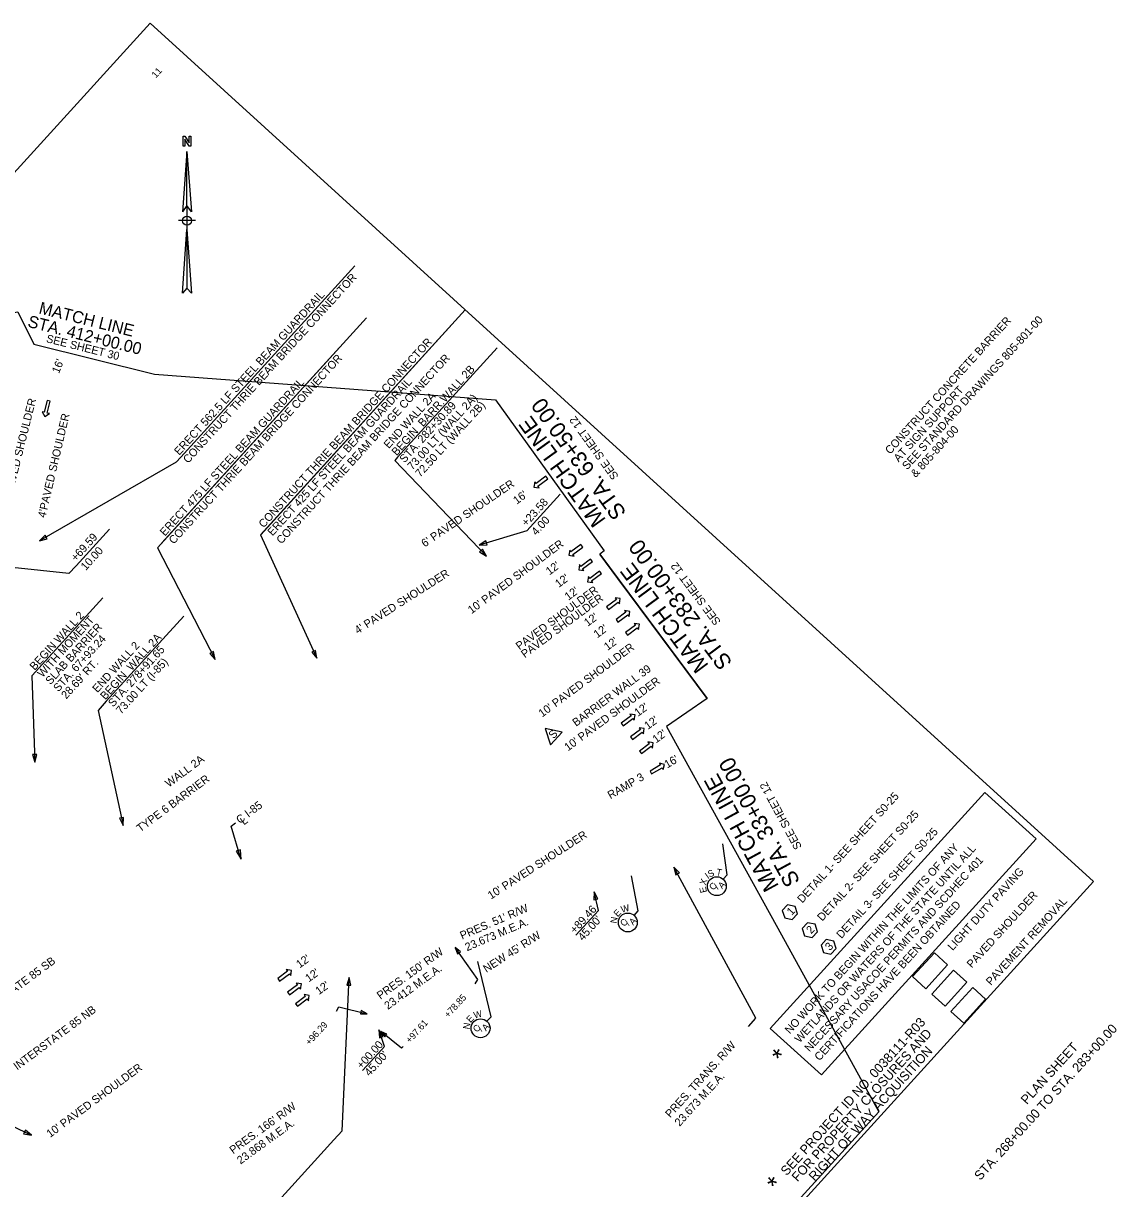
# Model space of a CAD drawing. Extents: x 1608705 to 1610581, y 1091647 to 1093887.
# Drawn here: x 1609761 to 1610581, y 1093011 to 1093885 of the extents above; entities that cross this region are included whole.
import ezdxf

# ---------------------------------------------------------------- set-up
doc = ezdxf.new("R2010")
doc.units = 0
for name, color, linetype in [('Level 1', 7, 'Continuous'), ('Level 14', 7, 'Continuous'), ('Level 2', 7, 'Continuous'), ('Plan_Clip', 7, 'Continuous'), ('RD_EX_Control_Access', 7, 'Continuous'), ('RD_EX_RW_TX', 7, 'Continuous'), ('RD_PD_GR_TX', 7, 'Continuous'), ('RD_PD_RW_TX', 7, 'Continuous'), ('RD_SHT_MatchLine', 7, 'Continuous'), ('RD_SHT_TX', 7, 'Continuous'), ('RD_TX_RoadID', 7, 'Continuous'), ('RD_TX_RW', 7, 'Continuous')]:
    doc.layers.add(name, color=color, linetype=linetype)

msp = doc.modelspace()

# ---------------------------------------------------------------- linework, layer by layer
at = {"layer": 'Level 1'}
for p, q in [((1609883.63, 1093788.5), (1609880.22, 1093743.19)), ((1609883.63, 1093747.84), (1609880.22, 1093743.19)), ((1609883.63, 1093747.84), (1609883.63, 1093730)), ((1609890.15, 1093736.61), (1609877.18, 1093736.61)), ((1609883.63, 1093730), (1609887.05, 1093682.16)), ((1609887.05, 1093682.16), (1609883.63, 1093685.99))]:
    msp.add_line(p, q, dxfattribs=at)
msp.add_lwpolyline([(1609886.57, 1093792.33), (1609885.34, 1093792.33), (1609881.92, 1093797.8), (1609881.92, 1093796.98), (1609881.92, 1093792.33), (1609880.69, 1093792.33), (1609880.69, 1093799.92), (1609881.92, 1093799.92), (1609885.34, 1093794.86), (1609885.34, 1093795.27), (1609885.34, 1093799.92), (1609886.57, 1093799.92), (1609886.57, 1093792.33)], dxfattribs=at)
for points in [[(1609883.63, 1093788.5), (1609887.05, 1093743.19), (1609883.63, 1093747.84)], [(1609883.63, 1093730), (1609883.63, 1093685.99), (1609880.22, 1093682.16)]]:
    msp.add_lwpolyline(points, close=True, dxfattribs=at)
msp.add_circle((1609883.67, 1093736.61), 3.45, dxfattribs=at)
at = {"layer": 'Level 14'}
for points in [[(1609781.09, 1093601.22), (1609778.76, 1093601.8), (1609776.55, 1093592.89), (1609774.97, 1093593.29), (1609777.03, 1093589.86), (1609780.46, 1093591.92), (1609778.87, 1093592.32)], [(1610154.27, 1093543.02), (1610152.84, 1093544.95), (1610145.48, 1093539.48), (1610144.51, 1093540.79), (1610143.93, 1093536.83), (1610147.88, 1093536.25), (1610146.91, 1093537.55)], [(1610180.49, 1093491.85), (1610179.06, 1093493.78), (1610171.69, 1093488.31), (1610170.72, 1093489.62), (1610170.14, 1093485.66), (1610174.1, 1093485.08), (1610173.13, 1093486.38)], [(1610187.82, 1093480.93), (1610186.39, 1093482.86), (1610179.03, 1093477.39), (1610178.06, 1093478.7), (1610177.48, 1093474.74), (1610181.43, 1093474.16), (1610180.46, 1093475.46)], [(1610194.52, 1093471.93), (1610193.09, 1093473.85), (1610185.72, 1093468.38), (1610184.75, 1093469.69), (1610184.17, 1093465.73), (1610188.13, 1093465.15), (1610187.16, 1093466.46)], [(1610198.36, 1093447.02), (1610199.79, 1093445.09), (1610207.15, 1093450.56), (1610208.12, 1093449.25), (1610208.7, 1093453.21), (1610204.75, 1093453.79), (1610205.72, 1093452.49)], [(1610205.48, 1093437.44), (1610206.91, 1093435.51), (1610214.27, 1093440.98), (1610215.24, 1093439.67), (1610215.82, 1093443.63), (1610211.87, 1093444.21), (1610212.84, 1093442.91)], [(1610212.65, 1093427.79), (1610214.08, 1093425.86), (1610221.44, 1093431.33), (1610222.41, 1093430.02), (1610223, 1093433.98), (1610219.04, 1093434.56), (1610220.01, 1093433.26)], [(1610209.38, 1093359.73), (1610210.82, 1093357.81), (1610218.17, 1093363.28), (1610219.15, 1093361.98), (1610219.73, 1093365.93), (1610215.77, 1093366.51), (1610216.74, 1093365.21)], [(1610216.36, 1093349.54), (1610217.79, 1093347.61), (1610225.15, 1093353.09), (1610226.12, 1093351.78), (1610226.7, 1093355.74), (1610222.75, 1093356.32), (1610223.72, 1093355.01)], [(1610223.08, 1093338.91), (1610224.52, 1093336.98), (1610231.88, 1093342.46), (1610232.85, 1093341.15), (1610233.43, 1093345.11), (1610229.47, 1093345.69), (1610230.44, 1093344.38)], [(1610231, 1093323.8), (1610232.21, 1093321.73), (1610240.13, 1093326.37), (1610240.95, 1093324.96), (1610241.96, 1093328.83), (1610238.09, 1093329.84), (1610238.91, 1093328.44)], [(1609951.7, 1093168.27), (1609953.14, 1093166.35), (1609960.5, 1093171.82), (1609961.47, 1093170.51), (1609962.05, 1093174.47), (1609958.09, 1093175.05), (1609959.07, 1093173.74)], [(1609959.12, 1093158.13), (1609960.55, 1093156.2), (1609967.91, 1093161.67), (1609968.88, 1093160.36), (1609969.46, 1093164.32), (1609965.51, 1093164.9), (1609966.48, 1093163.6)], [(1609965.06, 1093149.46), (1609966.49, 1093147.53), (1609973.86, 1093153), (1609974.83, 1093151.7), (1609975.41, 1093155.65), (1609971.45, 1093156.24), (1609972.42, 1093154.93)]]:
    msp.add_lwpolyline(points, close=True, dxfattribs=at)
at = {"layer": 'Level 2'}
msp.add_lwpolyline([(1608729.11, 1092645.4), (1609856.11, 1093884.55), (1610563.72, 1093240.99), (1609436.73, 1092001.83)], close=True, dxfattribs=at)
at = {"layer": 'Plan_Clip'}
msp.add_lwpolyline([(1609149.57, 1092364.39), (1609089.98, 1092453.43), (1608942.04, 1092657.59), (1608947.36, 1092661.14), (1608865.54, 1092773.4), (1609629.05, 1093625.07), (1609624.58, 1093628.85), (1609641.66, 1093647.8), (1609756.72, 1093668.33), (1609768.78, 1093644.04), (1609859.36, 1093621.37), (1610115.12, 1093602.27), (1610196.6, 1093489.1), (1610193.26, 1093486.62), (1610273.82, 1093378.23), (1610243.45, 1093357.42), (1610329.63, 1093200.98), (1610402.66, 1093068.39), (1609510.9, 1092089.32)], dxfattribs=at)
msp.add_lwpolyline([(1609149.57, 1092364.39), (1609089.98, 1092453.43), (1608942.04, 1092657.59), (1608947.36, 1092661.14), (1608865.54, 1092773.4), (1609629.05, 1093625.07), (1609624.58, 1093628.85), (1609641.66, 1093647.8), (1609756.72, 1093668.33), (1609768.78, 1093644.04), (1609859.36, 1093621.37), (1610115.12, 1093602.27), (1610196.6, 1093489.1), (1610193.26, 1093486.62), (1610273.82, 1093378.23), (1610243.45, 1093357.42), (1610329.63, 1093200.98), (1610402.66, 1093068.39), (1609510.9, 1092089.32)], dxfattribs=at)
at = {"layer": 'RD_EX_Control_Access'}
for p, q in [((1610288.92, 1093246.18), (1610285.73, 1093269.24)), ((1610222.14, 1093219.01), (1610217.11, 1093245.39)), ((1610285.84, 1093242.79), (1610288.92, 1093246.18)), ((1610219.06, 1093215.63), (1610222.14, 1093219.01)), ((1610111.72, 1093139.66), (1610101.86, 1093181.04)), ((1610108.64, 1093136.27), (1610111.72, 1093139.66))]:
    msp.add_line(p, q, dxfattribs=at)
for centre in [(1610281.07, 1093237.55), (1610214.3, 1093210.38), (1610103.87, 1093131.03)]:
    msp.add_circle(centre, 7.08, dxfattribs=at)
at = {"layer": 'RD_EX_RW_TX'}
for points in [[(1610304.85, 1093132.45), (1610310.35, 1093138.49), (1610248.96, 1093251.92)], [(1610099.9, 1093164.36), (1610101.88, 1093167.54), (1610084.89, 1093191.51)], [(1609995.8, 1093143.82), (1609997.59, 1093147.18), (1610018.75, 1093141.81)], [(1610045.72, 1093117.44), (1610044.63, 1093116.1), (1610029.02, 1093128.52)]]:
    msp.add_lwpolyline(points, dxfattribs=at)
for points in [[(1610253.08, 1093247.57), (1610248.96, 1093251.92), (1610250.35, 1093246.09)], [(1610088.74, 1093188.32), (1610084.89, 1093191.51), (1610086.62, 1093186.83)], [(1610013.75, 1093141.74), (1610018.75, 1093141.81), (1610014.39, 1093144.25)], [(1610033.61, 1093126.53), (1610029.02, 1093128.52), (1610032, 1093124.5)]]:
    msp.add_lwpolyline(points, close=True, dxfattribs=at)
at = {"layer": 'RD_PD_GR_TX'}
for p, q in [((1610009.48, 1093702.75), (1609878.96, 1093559.24)), ((1610092.37, 1093669.84), (1609938.92, 1093501.11)), ((1610018.27, 1093663.67), (1609864.82, 1093494.93))]:
    msp.add_line(p, q, dxfattribs=at)
for points in [[(1610092.37, 1093669.84), (1609938.75, 1093500.92), (1609981.02, 1093408.48)], [(1610018.27, 1093663.67), (1609861.42, 1093491.19), (1609904.7, 1093407.62)], [(1609878.96, 1093559.24), (1609875.55, 1093555.49), (1609773.08, 1093496.55)]]:
    msp.add_lwpolyline(points, dxfattribs=at)
for points in [[(1609777.33, 1093500.79), (1609773.08, 1093496.55), (1609778.88, 1093498.09)], [(1609900.66, 1093412.05), (1609904.7, 1093407.62), (1609903.41, 1093413.48)], [(1609977.2, 1093413.1), (1609981.02, 1093408.48), (1609980.02, 1093414.39)]]:
    msp.add_lwpolyline(points, close=True, dxfattribs=at)
at = {"layer": 'RD_SHT_MatchLine'}
for p, q in [((1609768.78, 1093644.04), (1609859.36, 1093621.37)), ((1610115.12, 1093602.27), (1610196.6, 1093489.1)), ((1610243.45, 1093357.42), (1610329.63, 1093200.98))]:
    msp.add_line(p, q, dxfattribs=at)
msp.add_lwpolyline([(1610273.82, 1093378.23), (1610206.95, 1093468.2), (1610193.26, 1093486.62)], dxfattribs=at)
at = {"layer": 'RD_SHT_TX'}
for p, q in [((1610116.29, 1093641.29), (1610041.65, 1093559.23)), ((1610163.55, 1093531.57), (1610138.48, 1093504.01)), ((1609825.55, 1093505.34), (1609800.48, 1093477.78)), ((1609820.54, 1093453.76), (1609770.13, 1093398.33)), ((1609881.17, 1093440.06), (1609823.1, 1093376.2)), ((1609993.85, 1093047.3), (1609878.33, 1092920.29))]:
    msp.add_line(p, q, dxfattribs=at)
for points in [[(1610041.65, 1093559.23), (1610039.46, 1093556.81), (1610108.21, 1093485.14)], [(1610138.48, 1093504.01), (1610138.48, 1093504.02), (1610102.81, 1093493.26)], [(1609800.48, 1093477.78), (1609795.13, 1093471.9), (1609730.94, 1093478.86)], [(1609770.22, 1093398.43), (1609767.33, 1093395.25), (1609769.63, 1093330.56)], [(1609823.1, 1093376.2), (1609816.9, 1093369.39), (1609835.67, 1093283.17)], [(1610437.89, 1093160.7), (1610454.22, 1093178.66), (1610444.27, 1093187.71), (1610427.94, 1093169.76), (1610437.89, 1093160.7)], [(1610452.27, 1093147.63), (1610468.6, 1093165.58), (1610458.64, 1093174.63), (1610442.31, 1093156.68), (1610452.27, 1093147.63)], [(1609993.85, 1093047.3), (1609999.97, 1093054.02), (1610005.32, 1093169.11)], [(1609702.19, 1093076.77), (1609705.22, 1093080.1), (1609767.01, 1093050.83)]]:
    msp.add_lwpolyline(points, dxfattribs=at)
for points in [[(1610107.91, 1093496.42), (1610102.81, 1093493.26), (1610108.8, 1093493.45)], [(1610103.08, 1093488.24), (1610108.21, 1093485.14), (1610105.32, 1093490.39)], [(1610152.31, 1093355.88), (1610156.27, 1093343.48), (1610165.03, 1093353.11)], [(1609767.87, 1093336.3), (1609769.63, 1093330.56), (1609770.97, 1093336.41)], [(1610321.19, 1093130.91), (1610482.17, 1093307.92), (1610520.53, 1093273.03), (1610359.55, 1093096.02)], [(1609832.92, 1093288.5), (1609835.67, 1093283.17), (1609835.96, 1093289.16)], [(1610339.82, 1093222.46), (1610334.14, 1093223.69), (1610330.23, 1093219.4), (1610332, 1093213.86), (1610337.67, 1093212.63), (1610341.58, 1093216.92)], [(1610354.77, 1093208.98), (1610349.1, 1093210.21), (1610345.19, 1093205.92), (1610346.96, 1093200.38), (1610352.63, 1093199.15), (1610356.54, 1093203.44)], [(1610368.88, 1093196.45), (1610363.2, 1093197.69), (1610359.29, 1093193.39), (1610361.06, 1093187.85), (1610366.74, 1093186.62), (1610370.65, 1093190.92)], [(1610437.89, 1093160.7), (1610454.22, 1093178.66), (1610444.27, 1093187.71), (1610427.94, 1093169.76)], [(1610452.27, 1093147.63), (1610468.6, 1093165.58), (1610458.64, 1093174.63), (1610442.31, 1093156.68)], [(1610006.6, 1093163.24), (1610005.32, 1093169.11), (1610003.5, 1093163.39)], [(1610466.37, 1093134.8), (1610482.7, 1093152.76), (1610473.02, 1093161.56), (1610456.69, 1093143.61)], [(1610466.35, 1093134.82), (1610482.68, 1093152.77), (1610473.02, 1093161.56), (1610456.69, 1093143.61)], [(1609761.11, 1093051.91), (1609767.01, 1093050.83), (1609762.44, 1093054.72)]]:
    msp.add_lwpolyline(points, close=True, dxfattribs=at)
at = {"layer": 'RD_TX_RoadID'}
msp.add_lwpolyline([(1609924.13, 1093257.97), (1609916.74, 1093282.66), (1609919.95, 1093285.05)], dxfattribs=at)
msp.add_lwpolyline([(1609923.91, 1093264.89), (1609920.61, 1093263.91), (1609924.24, 1093257.79)], close=True, dxfattribs=at)
at = {"layer": 'RD_TX_RW'}
for p, q in [((1610189.49, 1093216.3), (1610175.43, 1093200.84)), ((1610029.78, 1093115.22), (1610015.32, 1093099.32))]:
    msp.add_line(p, q, dxfattribs=at)
for points in [[(1610191.94, 1093228.04), (1610189.15, 1093233.35), (1610188.91, 1093227.36)], [(1610030.92, 1093124.94), (1610027.56, 1093129.92), (1610027.98, 1093123.93)]]:
    msp.add_lwpolyline(points, close=True, dxfattribs=at)
for points in [[(1610189.49, 1093216.3), (1610192.3, 1093219.39), (1610189.15, 1093233.35)], [(1610029.78, 1093115.22), (1610031.84, 1093117.49), (1610027.56, 1093129.92)]]:
    msp.add_lwpolyline(points, dxfattribs=at)

# ---------------------------------------------------------------- texts
at = {"layer": 'RD_EX_Control_Access'}
for s, rotation, p in [('S', 23.97318, (1610275.63, 1093243.98)), ('T', 348.8117, (1610280.32, 1093245.94)), ('X', 70.85514, (1610272.66, 1093237.97)), ('I', 35.69367, (1610274.44, 1093242.74)), ('E', 104.34226, (1610273.82, 1093233.26)), ('C', 47.71052, (1610278.43, 1093234.07)), ('/', 47.71052, (1610281.98, 1093234.84)), ('A', 47.71052, (1610285.14, 1093235.12)), ('W', 15.32234, (1610209.88, 1093217.56)), ('E', 47.1351, (1610206.76, 1093214.15)), ('N', 80.62222, (1610205.94, 1093209.37)), ('C', 47.71052, (1610211.65, 1093206.9)), ('/', 47.71052, (1610215.2, 1093207.67)), ('A', 47.71052, (1610218.36, 1093207.95)), ('E', 47.1351, (1610096.34, 1093134.8)), ('W', 15.32234, (1610099.46, 1093138.2)), ('N', 80.62222, (1610095.51, 1093130.02)), ('C', 47.71052, (1610101.23, 1093127.55)), ('/', 47.71052, (1610104.78, 1093128.32)), ('A', 47.71052, (1610107.94, 1093128.59))]:
    msp.add_text(s, height=5, rotation=rotation, dxfattribs=at).set_placement(p)
at = {"layer": 'RD_EX_RW_TX'}
for s, height, rotation, p in [("PRES. 51' R/W", 6, 23.19549, (1610089.99, 1093197.47)), ('23.673 M.E.A.', 6, 23.19549, (1610093.74, 1093188.74)), ("PRES. 150' R/W", 6, 35.9902, (1610028.77, 1093152.4)), ('23.412 M.E.A.', 6, 35.9902, (1610034.35, 1093144.71)), ('+78.85', 5, 47.71377, (1610079.74, 1093138.47)), ('+97.61', 5, 47.71377, (1610050.93, 1093119.46)), ('+96.29', 5, 47.71377, (1609975.64, 1093117.93)), ('PRES. TRANS. R/W ', 6, 47.71377, (1610246.18, 1093063.48)), ('23.673 M.E.A.', 6, 47.71377, (1610253.21, 1093057.09)), ("PRES. 166' R/W", 6, 35.9902, (1609918.24, 1093036.49)), ('23.868 M.E.A.', 6, 35.9902, (1609923.83, 1093028.8))]:
    msp.add_text(s, height=height, rotation=rotation, dxfattribs=at).set_placement(p)
at = {"layer": 'RD_PD_GR_TX'}
for s, p in [('CONSTRUCT THRIE BEAM BRIDGE CONNECTOR', (1609884.51, 1093554.19)), ('ERECT 562.5 LF STEEL BEAM GUARDRAIL', (1609877.85, 1093560.25)), ('CONSTRUCT THRIE BEAM BRIDGE CONNECTOR', (1609941.17, 1093505.81)), ('CONSTRUCT THRIE BEAM BRIDGE CONNECTOR', (1609873.73, 1093493.59)), ('CONSTRUCT THRIE BEAM BRIDGE CONNECTOR', (1609954.49, 1093493.7)), ('ERECT 475 LF STEEL BEAM GUARDRAIL', (1609867.07, 1093499.64)), ('ERECT 425 LF STEEL BEAM GUARDRAIL', (1609947.83, 1093499.76))]:
    msp.add_text(s, height=6, rotation=47.7154, dxfattribs=at).set_placement(p)
at = {"layer": 'RD_PD_RW_TX'}
msp.add_text("NEW 45' R/W", height=6, rotation=32.90167, dxfattribs=at).set_placement((1610108.23, 1093172.49))
at = {"layer": 'RD_SHT_MatchLine'}
for s, height, rotation, p in [('MATCH LINE', 9, 345.96146, (1609771.94, 1093667.13)), ('STA. 412+00.00', 9, 345.96146, (1609763.58, 1093657.06)), ('SEE SHEET 30', 6, 345.93804, (1609777.61, 1093645.55)), ('STA. 63+50.00', 12, 125.77953, (1610213.69, 1093517.77)), ('MATCH LINE', 12, 125.77953, (1610198.28, 1093512.25)), ('SEE SHEET 12', 6, 125.75611, (1610207.72, 1093545.03)), ('STA. 283+00.00', 12, 126.62559, (1610293.24, 1093405.46)), ('MATCH LINE', 12, 126.62559, (1610275.41, 1093403.08)), ('SEE SHEET 12', 6, 126.60217, (1610284.37, 1093435.99)), ('STA. 33+00.00', 12, 118.54773, (1610343.91, 1093241.14)), ('MATCH LINE', 12, 118.54773, (1610327.93, 1093237.61)), ('SEE SHEET 12', 6, 118.599, (1610345.08, 1093267.05))]:
    msp.add_text(s, height=height, rotation=rotation, dxfattribs=at).set_placement(p)
at = {"layer": 'RD_SHT_TX'}
for s, height, rotation, p in [('11', 5, 47.71377, (1609860.28, 1093843.18)), ('CONSTRUCT CONCRETE BARRIER ', 6, 47.71377, (1610411.11, 1093561.01)), ('SEE STANDARD DRAWINGS 805-801-00', 6, 47.71377, (1610423.9, 1093549.37)), ("16'", 6, 67.8513, (1609787.54, 1093621.56)), ('BEGIN  BARR.WALL 2B', 6, 47.71377, (1610040.91, 1093559.9)), ('AT SIGN SUPPORT', 6, 47.71377, (1610417.5, 1093555.19)), ("10' PAVED SHOULDER", 6, 75.96126, (1609749.53, 1093518.44)), ('END WALL 2A', 6, 47.71377, (1610035, 1093565.28)), ('STA. 282+30.89', 6, 47.71377, (1610046.83, 1093554.52)), ('73.00 LT (WALL 2A)', 6, 47.71377, (1610052.75, 1093549.14)), ('72.50 LT (WALL 2B)', 6, 47.71377, (1610058.67, 1093543.75)), ("4'PAVED SHOULDER", 6, 76.81923, (1609777.41, 1093513.41)), ('& 805-804-00', 6, 47.71377, (1610430.29, 1093543.56)), ("6' PAVED SHOULDER", 6, 34.38288, (1610061.98, 1093491.46)), ("16'", 6, 36.62822, (1610131.06, 1093523.6)), ('+23.58', 6, 47.71377, (1610138.34, 1093506.84)), ('4.00', 6, 47.71377, (1610145.74, 1093500.11)), ('+69.59', 6, 47.71377, (1609800.34, 1093480.61)), ("10' PAVED SHOULDER", 6, 36.51555, (1610097.09, 1093441.46)), ('10.00', 6, 47.71377, (1609807.74, 1093473.88)), ("12'", 6, 36.62822, (1610155.58, 1093470.53)), ("4' PAVED SHOULDER", 6, 32.58648, (1610011.74, 1093426.35)), ("12'", 6, 36.62822, (1610162.54, 1093461.16)), ('PAVED SHOULDER', 6, 36.45274, (1610133.04, 1093414.4)), ("12'", 6, 36.62822, (1610169.7, 1093451.54)), ('PAVED SHOULDER', 6, 36.45274, (1610137.03, 1093408.43)), ('BEGIN WALL 2', 6, 47.71377, (1609769.39, 1093399)), ("12'", 6, 36.62822, (1610184.24, 1093431.98)), ('WITH MOMENT', 6, 47.71377, (1609775.3, 1093393.62)), ('SLAB BARRIER', 6, 47.71377, (1609781.22, 1093388.23)), ("12'", 6, 36.62154, (1610191.4, 1093423.32)), ('STA. 67+93.24', 6, 47.71377, (1609787.14, 1093382.85)), ('BEGIN  WALL 2A', 6, 47.71377, (1609822.36, 1093376.87)), ("12'", 6, 36.62154, (1610199.15, 1093413.93)), ('END WALL 2', 6, 47.71377, (1609816.44, 1093382.26)), ('STA. 278+91.65', 6, 47.71377, (1609828.28, 1093371.49)), ("10' PAVED SHOULDER", 6, 36.51555, (1610150.07, 1093363.98)), ('73.00 LT (I-85)', 6, 47.71377, (1609834.2, 1093366.11)), ("28.69' RT.", 6, 47.71377, (1609793.06, 1093377.47)), ('BARRIER WALL 39', 6, 36.62559, (1610175.5, 1093357.04)), ("10' PAVED SHOULDER", 6, 36.51555, (1610169.45, 1093338.58)), ("12'", 6, 36.22423, (1610221.94, 1093364.53)), ("12'", 6, 36.22423, (1610229.4, 1093354.72)), ('S', 6, 47.71377, (1610158.64, 1093347.57)), ("12'", 6, 36.22423, (1610235.55, 1093344.55)), ('WALL 2A', 6, 36.62559, (1609870.01, 1093311.38)), ("16'", 6, 30.39517, (1610243.89, 1093325.8)), ('TYPE 6 BARRIER', 6, 36.62559, (1609848.62, 1093277.73)), ('DETAIL 1- SEE SHEET S0-25', 6, 47.71377, (1610345.23, 1093224.53)), ('DETAIL 2- SEE SHEET S0-25', 6, 47.71377, (1610360.21, 1093210.91)), ("10' PAVED SHOULDER", 6, 32.94677, (1610111.65, 1093227.48)), ('DETAIL 3- SEE SHEET S0-25', 6, 47.71377, (1610374.54, 1093197.87)), ('NO WORK TO BEGIN WITHIN THE LIMITS OF ANY', 6, 47.71527, (1610335.9, 1093126.39)), ('WETLANDS OR WATERS OF THE STATE UNTIL ALL', 6, 47.71527, (1610343.29, 1093119.66)), ('NECESSARY USACOE PERMITS AND SCDHEC 401', 6, 47.71527, (1610350.69, 1093112.93)), ('LIGHT DUTY PAVING', 6, 47.71377, (1610457.99, 1093188.86)), ('PAVED SHOULDER', 6, 47.71377, (1610472.37, 1093175.78)), ('CERTIFICATIONS HAVE BEEN OBTAINED', 6, 47.71527, (1610358.09, 1093106.2)), ('PAVEMENT REMOVAL', 6, 47.71377, (1610486.75, 1093162.71)), ('1', 6, 47.71377, (1610337.28, 1093215.21)), ('2', 6, 47.71377, (1610351.91, 1093201.37)), ('3', 6, 47.71377, (1610366.01, 1093188.84)), ("12'", 6, 35.64424, (1609968.16, 1093175.85)), ("12'", 6, 35.64424, (1609974.99, 1093165.39)), ("12'", 6, 35.64424, (1609982.59, 1093155.87)), ("10' PAVED SHOULDER", 6, 36.51555, (1609780.99, 1093048.77))]:
    msp.add_text(s, height=height, rotation=rotation, dxfattribs=at).set_placement(p)
at = {"layer": 'RD_TX_RoadID'}
for s, height, rotation, p in [('RAMP 3', 6, 30.15532, (1610201.3, 1093302.71)), ('C I-85', 6, 36.62005, (1609923.27, 1093284.05)), ('L', 6, 36.62005, (1609926.3, 1093283.06)), ('INTERSTATE 85 SB', 6, 36.62005, (1609726.15, 1093136.19)), ('INTERSTATE 85 NB', 6, 36.62005, (1609756.27, 1093099.35)), ('STA. 268+00.00 TO STA. 283+00.00', 6.9833, 47.74972, (1610478.68, 1093016.52)), ('PLAN SHEET', 6.983, 47.74972, (1610513.62, 1093073.44))]:
    msp.add_text(s, height=height, rotation=rotation, dxfattribs=at).set_placement(p)
at = {"layer": 'RD_TX_RW'}
for s, height, rotation, p in [('+89.46', 6, 47.71377, (1610174.73, 1093201.55)), ("45.00'", 6, 47.71377, (1610180.65, 1093196.17)), ('SEE PROJECT ID NO. 0038111-R03', 7, 47.71377, (1610333.48, 1093020.06)), ('FOR PROPERTY CLOSURES AND', 7, 47.71377, (1610341.72, 1093015.48)), ('+00.00', 6, 47.71377, (1610014.64, 1093100.06)), ("45.00'", 6, 47.71377, (1610020.56, 1093094.68)), ('*', 14, 42.79735, (1610330.51, 1093102.15)), ('RIGHT OF WAY ACQUISITION', 7, 47.71377, (1610354.53, 1093015.92)), ('*', 14, 42.79735, (1610326.76, 1093006.28))]:
    msp.add_text(s, height=height, rotation=rotation, dxfattribs=at).set_placement(p)

doc.saveas('drawing.dxf')
